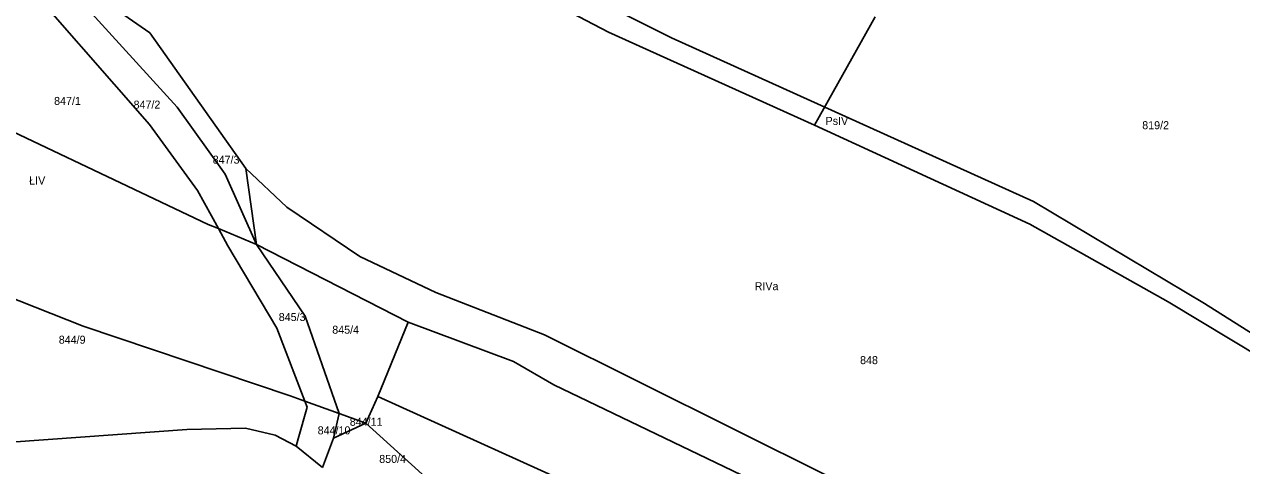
# Model space of a CAD drawing. Extents: x 7498273 to 7499989, y 5499795 to 5500810.
# Drawn here: x 7499540.8 to 7499768.9, y 5500223.1 to 5500305.7 of the extents above; entities that cross this region are included whole.
import ezdxf

# ---------------------------------------------------------------- set-up
doc = ezdxf.new("R2010")
doc.units = 0
for name, color, linetype in [('209-oznaczenie konturu klasyfikacyjnego', 7, 'Continuous'), ('211-numer działki ewidencyjnej', 7, 'Continuous'), ('217-kontur klasyfikacyjny', 7, 'Continuous'), ('218-kontur użytku gruntowego', 7, 'Continuous'), ('219-działka ewidencyjna', 7, 'Continuous')]:
    doc.layers.add(name, color=color, linetype=linetype)

msp = doc.modelspace()

# ---------------------------------------------------------------- linework, layer by layer
at = {"layer": '217-kontur klasyfikacyjny'}
for points in [[(7499650.25, 5500304.22), (7499604.11, 5500328.35)], [(7499662.05, 5500303.12), (7499623.46, 5500322.52)], [(7499543.84, 5500318.32), (7499564.29, 5500304.05)], [(7499564.29, 5500304.05), (7499582.32, 5500278.68)], [(7499688.83, 5500286.77), (7499650.25, 5500304.22)], [(7499729.91, 5500272.49), (7499662.05, 5500303.12)], [(7499729.24, 5500268.29), (7499688.83, 5500286.77)], [(7499582.32, 5500278.68), (7499590.01, 5500271.45)], [(7499582.32, 5500278.68), (7499584.3, 5500264.46)], [(7499761.94, 5500253.41), (7499729.91, 5500272.49)], [(7499590.01, 5500271.45), (7499603.65, 5500262.24)], [(7499755.15, 5500253.71), (7499729.24, 5500268.29)], [(7499551.8, 5500249.17), (7499509.82, 5500265.78)], [(7499584.3, 5500264.46), (7499612.7, 5500249.92)], [(7499603.65, 5500262.24), (7499617.91, 5500255.47)], [(7499617.91, 5500255.47), (7499638.25, 5500247.53)], [(7499784.49, 5500236.07), (7499755.15, 5500253.71)], [(7499820.43, 5500216.51), (7499761.94, 5500253.41)], [(7499590.6, 5500236.14), (7499551.8, 5500249.17)], [(7499612.7, 5500249.92), (7499607.01, 5500236.03)], [(7499612.7, 5500249.92), (7499632.47, 5500242.57)], [(7499638.25, 5500247.53), (7499709.49, 5500212.1)], [(7499632.47, 5500242.57), (7499640, 5500238.18)], [(7499640, 5500238.18), (7499679.94, 5500219.03)], [(7499593.38, 5500235.15), (7499590.6, 5500236.14)], [(7499599.79, 5500232.83), (7499593.38, 5500235.15)], [(7499607.01, 5500236.03), (7499604.8, 5500231.05)], [(7499604.8, 5500231.05), (7499599.79, 5500232.83)], [(7499518.38, 5500226), (7499571.25, 5500229.86)], [(7499571.25, 5500229.86), (7499582.22, 5500230.06)], [(7499582.22, 5500230.06), (7499587.81, 5500228.77)], [(7499587.81, 5500228.77), (7499591.75, 5500226.72)], [(7499591.75, 5500226.72), (7499596.65, 5500222.71)]]:
    msp.add_lwpolyline(points, dxfattribs=at)
at = {"layer": '218-kontur użytku gruntowego'}
for points in [[(7499650.25, 5500304.22), (7499604.11, 5500328.35)], [(7499662.05, 5500303.12), (7499623.46, 5500322.52)], [(7499543.84, 5500318.32), (7499564.29, 5500304.05)], [(7499564.29, 5500304.05), (7499582.32, 5500278.68)], [(7499688.83, 5500286.77), (7499650.25, 5500304.22)], [(7499729.91, 5500272.49), (7499662.05, 5500303.12)], [(7499729.24, 5500268.29), (7499688.83, 5500286.77)], [(7499582.32, 5500278.68), (7499590.01, 5500271.45)], [(7499582.32, 5500278.68), (7499584.3, 5500264.46)], [(7499761.94, 5500253.41), (7499729.91, 5500272.49)], [(7499590.01, 5500271.45), (7499603.65, 5500262.24)], [(7499755.15, 5500253.71), (7499729.24, 5500268.29)], [(7499551.8, 5500249.17), (7499509.82, 5500265.78)], [(7499584.3, 5500264.46), (7499612.7, 5500249.92)], [(7499603.65, 5500262.24), (7499617.91, 5500255.47)], [(7499617.91, 5500255.47), (7499638.25, 5500247.53)], [(7499784.49, 5500236.07), (7499755.15, 5500253.71)], [(7499820.43, 5500216.51), (7499761.94, 5500253.41)], [(7499590.6, 5500236.14), (7499551.8, 5500249.17)], [(7499612.7, 5500249.92), (7499607.01, 5500236.03)], [(7499612.7, 5500249.92), (7499632.47, 5500242.57)], [(7499638.25, 5500247.53), (7499709.49, 5500212.1)], [(7499632.47, 5500242.57), (7499640, 5500238.18)], [(7499640, 5500238.18), (7499679.94, 5500219.03)], [(7499593.38, 5500235.15), (7499590.6, 5500236.14)], [(7499599.79, 5500232.83), (7499593.38, 5500235.15)], [(7499607.01, 5500236.03), (7499604.8, 5500231.05)], [(7499604.8, 5500231.05), (7499599.79, 5500232.83)], [(7499518.38, 5500226), (7499571.25, 5500229.86)], [(7499571.25, 5500229.86), (7499582.22, 5500230.06)], [(7499582.22, 5500230.06), (7499587.81, 5500228.77)], [(7499587.81, 5500228.77), (7499591.75, 5500226.72)], [(7499591.75, 5500226.72), (7499596.65, 5500222.71)]]:
    msp.add_lwpolyline(points, dxfattribs=at)
at = {"layer": '219-działka ewidencyjna'}
for points in [[(7499650.25, 5500304.22), (7499604.11, 5500328.35)], [(7499543.84, 5500318.32), (7499569.45, 5500290.17)], [(7499543.84, 5500318.32), (7499564.29, 5500304.05)], [(7499538.24, 5500316.71), (7499564.26, 5500286.9)], [(7499688.83, 5500286.77), (7499700.2, 5500307.1)], [(7499564.29, 5500304.05), (7499582.32, 5500278.68)], [(7499650.25, 5500304.22), (7499688.83, 5500286.77)], [(7499575.27, 5500268.23), (7499523.41, 5500292.76)], [(7499569.45, 5500290.17), (7499578.42, 5500277.64)], [(7499564.26, 5500286.9), (7499573.25, 5500274.59)], [(7499729.24, 5500268.29), (7499688.83, 5500286.77)], [(7499582.32, 5500278.68), (7499584.3, 5500264.46)], [(7499578.42, 5500277.64), (7499584.3, 5500264.46)], [(7499573.25, 5500274.59), (7499577.17, 5500267.44)], [(7499575.27, 5500268.23), (7499577.17, 5500267.44)], [(7499577.17, 5500267.44), (7499578.93, 5500264.22)], [(7499577.17, 5500267.44), (7499584.3, 5500264.46)], [(7499729.24, 5500268.29), (7499755.15, 5500253.71)], [(7499509.82, 5500265.78), (7499551.8, 5500249.17)], [(7499578.93, 5500264.22), (7499588.11, 5500248.8)], [(7499584.3, 5500264.46), (7499612.7, 5500249.92)], [(7499584.3, 5500264.46), (7499593.42, 5500251.06)], [(7499755.15, 5500253.71), (7499784.49, 5500236.07)], [(7499593.42, 5500251.06), (7499599.79, 5500232.83)], [(7499551.8, 5500249.17), (7499590.6, 5500236.14)], [(7499588.11, 5500248.8), (7499593.38, 5500235.15)], [(7499607.01, 5500236.03), (7499612.7, 5500249.92)], [(7499632.47, 5500242.57), (7499612.7, 5500249.92)], [(7499632.47, 5500242.57), (7499640, 5500238.18)], [(7499640, 5500238.18), (7499679.94, 5500219.03)], [(7499590.6, 5500236.14), (7499593.38, 5500235.15)], [(7499593.38, 5500235.15), (7499599.79, 5500232.83)], [(7499593.38, 5500235.15), (7499593.8, 5500234.03)], [(7499604.8, 5500231.05), (7499607.01, 5500236.03)], [(7499607.01, 5500236.03), (7499652.96, 5500215.21)], [(7499592.13, 5500228.08), (7499593.8, 5500234.03)], [(7499598.76, 5500228.23), (7499599.79, 5500232.83)], [(7499604.8, 5500231.05), (7499599.79, 5500232.83)], [(7499604.8, 5500231.05), (7499598.76, 5500228.23)], [(7499604.8, 5500231.05), (7499617.95, 5500219.11)], [(7499518.38, 5500226), (7499571.25, 5500229.86)], [(7499571.25, 5500229.86), (7499582.22, 5500230.06)], [(7499582.22, 5500230.06), (7499587.81, 5500228.77)], [(7499587.81, 5500228.77), (7499591.75, 5500226.72)], [(7499596.65, 5500222.71), (7499598.76, 5500228.23)], [(7499591.75, 5500226.72), (7499592.13, 5500228.08)], [(7499591.75, 5500226.72), (7499596.65, 5500222.71)]]:
    msp.add_lwpolyline(points, dxfattribs=at)

# ---------------------------------------------------------------- texts
at = {"layer": '209-oznaczenie konturu klasyfikacyjnego'}
for s, p in [('PsIV', (7499690.94, 5500286.84)), ('ŁIV', (7499541.72, 5500275.69)), ('RIVa', (7499677.65, 5500255.91))]:
    msp.add_text(s, height=1.5, dxfattribs=at).set_placement(p)
at = {"layer": '211-numer działki ewidencyjnej'}
for s, p in [('847/1', (7499546.38, 5500290.58)), ('847/2', (7499561.27, 5500289.89)), ('819/2', (7499750.27, 5500286.04)), ('847/3', (7499576.1, 5500279.59)), ('845/3', (7499588.48, 5500250.14)), ('845/4', (7499598.5, 5500247.76)), ('844/9', (7499547.26, 5500245.89)), ('848', (7499697.4, 5500242.07)), ('844/10', (7499595.77, 5500228.93)), ('844/11', (7499601.78, 5500230.53)), ('850/4', (7499607.3, 5500223.58))]:
    msp.add_text(s, height=1.5, dxfattribs=at).set_placement(p)

doc.saveas('drawing.dxf')
